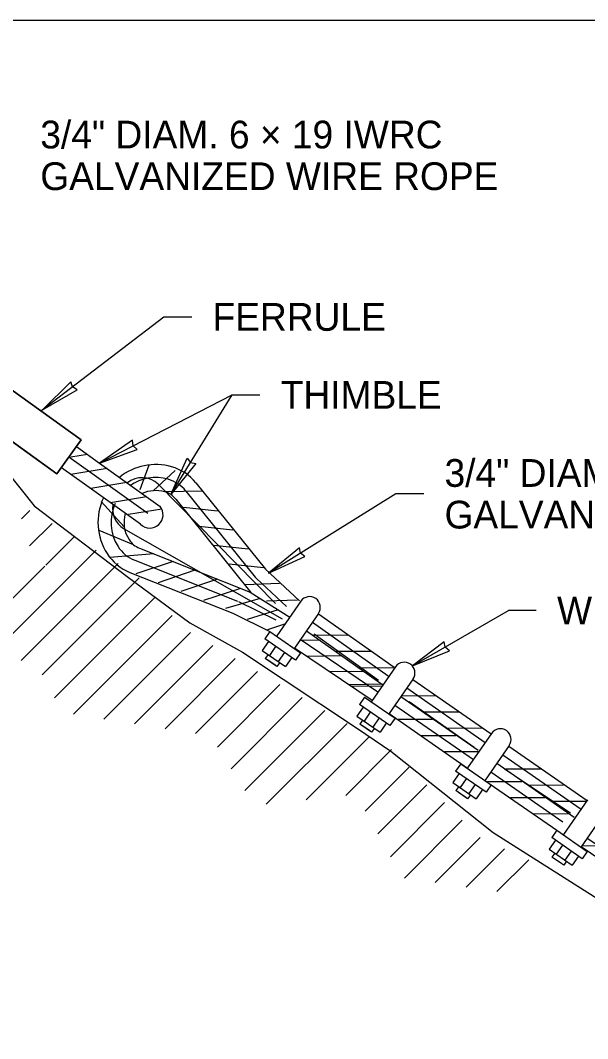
# Model space of a CAD drawing. Extents: x 99861 to 103151, y 100000 to 102076.
# Drawn here: x 102177 to 102504, y 101489 to 102076 of the extents above; entities that cross this region are included whole.
import ezdxf

# ---------------------------------------------------------------- set-up
doc = ezdxf.new("R2010")
doc.units = 0
for name, color, linetype in [('Level 1', 7, 'Continuous'), ('Level 10', 7, 'Continuous'), ('Level 15', 7, 'Continuous'), ('Level 2', 7, 'Continuous'), ('Level 20', 7, 'Continuous'), ('Level 28', 7, 'Continuous'), ('Level 4', 7, 'Continuous'), ('Level 6', 7, 'Continuous')]:
    doc.layers.add(name, color=color, linetype=linetype)

msp = doc.modelspace()

# ---------------------------------------------------------------- linework, layer by layer
at = {"layer": 'Level 1'}
for p, q in [((102272.77, 101804.76), (102312.73, 101755.09)), ((102278.62, 101809.46), (102318.58, 101759.79)), ((102266.93, 101800.05), (102310.31, 101746.26)), ((102258.12, 101795.77), (102257.97, 101795.92)), ((102246.65, 101785.56), (102246.57, 101785.62)), ((102246.07, 101771.82), (102309.84, 101746.44)), ((102243.3, 101764.85), (102302.6, 101741.33)), ((102240.54, 101757.87), (102299.83, 101734.36)), ((102318.58, 101759.79), (102338.23, 101741.48)), ((102312.73, 101755.09), (102313.46, 101754.3)), ((102313.46, 101754.3), (102330.76, 101738.18)), ((102309.84, 101746.44), (102332.64, 101732.08)), ((102303.16, 101741.08), (102324.6, 101730.46)), ((102299.83, 101734.36), (102321.26, 101723.74)), ((102349.18, 101734.05), (102392.74, 101703.2)), ((102342.24, 101724.26), (102386.33, 101693.03)), ((102346.78, 101722.36), (102383.82, 101695.69)), ((102403.55, 101696.18), (102448.69, 101664.77)), ((102396.69, 101686.33), (102441.26, 101655.32)), ((102401.4, 101683.38), (102438.84, 101657.18)), ((102389.84, 101676.48), (102435.01, 101645.05)), ((102458.83, 101657.71), (102503.96, 101626.31)), ((102451.96, 101647.87), (102496.57, 101616.83)), ((102456.42, 101644.7), (102494.31, 101619.21)), ((102445.11, 101638.02), (102486.48, 101609.23))]:
    msp.add_line(p, q, dxfattribs=at)
msp.add_lwpolyline([(99861, 100000), (103150, 100000), (103150, 102076), (99861, 102076)], close=True, dxfattribs=at)
for points in [[(102209.8, 101830.34), (102223.04, 101820.9), (102257.97, 101795.92)], [(102246.57, 101785.62), (102214.34, 101808.71), (102201.05, 101818.17)], [(102380.05, 101683.97), (102335.32, 101714.27)], [(102595.8, 101535.23), (102500.53, 101599.76)]]:
    msp.add_lwpolyline(points, dxfattribs=at)
for centre, radius, start, end in [((102255.49, 101786.67), 33.34, 74.16645, 128.84498), ((102257.03, 101792.09), 27.7, 38.8173, 74.16645), ((102255.49, 101786.67), 25.84, 74.16645, 125.28472), ((102257.03, 101792.09), 20.2, 38.8173, 74.16645), ((102255.49, 101786.67), 18.34, 74.16645, 115.23491), ((102257.03, 101792.09), 12.7, 38.8173, 74.16645), ((102255.49, 101786.67), 33.34, 154.83818, 212.69583), ((102255.49, 101786.67), 25.84, 154.83818, 212.69583), ((102251.96, 101791.13), 7.69, 226.37495, 38.53222), ((102255.49, 101786.67), 18.34, 163.64194, 212.69583), ((102250.75, 101783.63), 12.7, 212.69583, 248.36701), ((102250.75, 101783.63), 20.2, 212.69583, 248.36701), ((102250.75, 101783.63), 27.7, 212.69583, 248.36701)]:
    msp.add_arc(centre, radius, start, end, dxfattribs=at)
at = {"layer": 'Level 10'}
for p, q in [((102178.08, 101788.73), (102182.96, 101793.61)), ((102182.8, 101773.08), (102195.69, 101785.97)), ((102194.11, 101784.39), (102195.69, 101785.97)), ((102192.1, 101762.02), (102208.41, 101778.33)), ((102158.82, 101708.38), (102221.14, 101770.7)), ((102177.96, 101707.15), (102233.87, 101763.06)), ((102177.96, 101707.15), (102233.87, 101763.06)), ((102139.68, 101709.6), (102191.52, 101761.43)), ((102189.94, 101698.76), (102245.85, 101754.67)), ((102197.15, 101685.61), (102255.39, 101743.85)), ((102207.99, 101676.08), (102264.94, 101733.03)), ((102207.99, 101676.08), (102264.94, 101733.03)), ((102225.58, 101673.32), (102275.4, 101723.14)), ((102243.18, 101670.55), (102288.3, 101715.67)), ((102260.78, 101667.78), (102301.19, 101708.19)), ((102260.78, 101667.78), (102301.19, 101708.19)), ((102278.37, 101665.01), (102314.09, 101700.72)), ((102290.94, 101657.21), (102326.98, 101693.25)), ((102298.82, 101644.73), (102339.88, 101685.78)), ((102298.82, 101644.73), (102339.88, 101685.78)), ((102306.7, 101632.25), (102352.77, 101678.31)), ((102319.14, 101624.32), (102365.66, 101670.84)), ((102342.03, 101626.84), (102378.56, 101663.37)), ((102342.03, 101626.84), (102378.56, 101663.37)), ((102364.91, 101629.36), (102391.27, 101655.72)), ((102376.17, 101620.25), (102401.46, 101645.54)), ((102383.39, 101607.11), (102411.64, 101635.36)), ((102383.39, 101607.11), (102411.64, 101635.36)), ((102390.6, 101593.96), (102421.82, 101625.18)), ((102398.73, 101581.72), (102432, 101614.99)), ((102416.48, 101579.1), (102442.44, 101605.07)), ((102416.48, 101579.1), (102442.44, 101605.07)), ((102434.22, 101576.49), (102456.38, 101598.64)), ((102451.97, 101573.87), (102470.31, 101592.21))]:
    msp.add_line(p, q, dxfattribs=at)
at = {"layer": 'Level 15'}
for p, q in [((102189.31, 101850.88), (102260.16, 101905.1)), ((102260.16, 101905.1), (102276.16, 101905.1)), ((102223.04, 101820.9), (102299.47, 101860.13)), ((102264.04, 101802.68), (102299.47, 101860.13)), ((102299.47, 101860.13), (102315.47, 101860.13)), ((102393.82, 101803.16), (102320.42, 101757.49)), ((102409.82, 101803.16), (102393.82, 101803.16)), ((102403.34, 101703.92), (102458.64, 101735.85)), ((102474.64, 101735.85), (102458.64, 101735.85))]:
    msp.add_line(p, q, dxfattribs=at)
for points in [[(102190.15, 101851.52), (102210.1, 101863.03), (102207.44, 101864.76), (102206.47, 101867.77)], [(102223.04, 101820.9), (102244.72, 101828.67), (102242.41, 101830.84), (102241.99, 101833.98)], [(102264.04, 101802.68), (102273.49, 101823.68), (102275.47, 101821.22), (102278.57, 101820.55)], [(102320.42, 101757.49), (102341.38, 101767.02), (102338.91, 101768.99), (102338.23, 101772.09)], [(102403.34, 101703.92), (102424.61, 101712.75), (102422.2, 101714.81), (102421.62, 101717.92)]]:
    msp.add_lwpolyline(points, close=True, dxfattribs=at)
at = {"layer": 'Level 2'}
msp.add_lwpolyline([(102109.55, 101851.4), (102143.61, 101827.11), (102169.61, 101815.92), (102185.33, 101796.3), (102238.99, 101755.45), (102275, 101728.75), (102305.41, 101711.87), (102328.83, 101696.29), (102371.7, 101667.89), (102390.96, 101654.77), (102398.39, 101648.87), (102449.8, 101608.01), (102535.32, 101553.7), (102542.03, 101551.35)], dxfattribs=at)
at = {"layer": 'Level 28'}
for p, q in [((102339.06, 101741.26), (102325.2, 101721.28)), ((102349.17, 101734.24), (102335.32, 101714.27)), ((102321.26, 101723.74), (102338.78, 101711.55)), ((102335.88, 101707.36), (102318.34, 101719.53)), ((102320.12, 101710.57), (102318.52, 101708.26)), ((102324.5, 101715.12), (102320.94, 101709.99)), ((102329.55, 101711.75), (102325.94, 101706.53)), ((102325.26, 101703.58), (102318.52, 101708.26)), ((102324.2, 101704.32), (102320.03, 101707.21)), ((102326.86, 101705.89), (102325.26, 101703.58)), ((102333.77, 101708.83), (102330.15, 101703.61)), ((102393.58, 101703.47), (102379.72, 101683.5)), ((102403.69, 101696.45), (102389.84, 101676.48)), ((102390.4, 101669.57), (102372.87, 101681.74)), ((102375.79, 101685.95), (102393.3, 101673.76)), ((102379.02, 101677.33), (102375.47, 101672.2)), ((102374.64, 101672.78), (102373.04, 101670.47)), ((102379.79, 101665.79), (102373.04, 101670.47)), ((102378.72, 101666.53), (102374.56, 101669.42)), ((102384.08, 101673.96), (102380.46, 101668.74)), ((102388.29, 101671.04), (102384.67, 101665.82)), ((102381.38, 101668.1), (102379.79, 101665.79)), ((102448.92, 101665.11), (102435.07, 101645.14)), ((102459.04, 101658.09), (102445.18, 101638.12)), ((102431.13, 101647.59), (102448.65, 101635.4)), ((102445.74, 101631.22), (102428.21, 101643.38)), ((102429.99, 101634.42), (102428.39, 101632.11)), ((102434.37, 101638.97), (102430.81, 101633.84)), ((102439.42, 101635.6), (102435.8, 101630.38)), ((102435.13, 101627.44), (102428.39, 101632.11)), ((102434.06, 101628.18), (102429.9, 101631.06)), ((102436.73, 101629.74), (102435.13, 101627.44)), ((102443.64, 101632.68), (102440.02, 101627.46)), ((102504.27, 101626.75), (102490.41, 101606.78)), ((102514.38, 101619.74), (102500.53, 101599.76)), ((102501.09, 101592.86), (102483.55, 101605.02)), ((102486.48, 101609.23), (102503.99, 101597.05)), ((102489.71, 101600.61), (102486.16, 101595.49)), ((102485.33, 101596.06), (102483.73, 101593.75)), ((102490.47, 101589.08), (102483.73, 101593.75)), ((102494.77, 101597.24), (102491.15, 101592.02)), ((102498.98, 101594.32), (102495.36, 101589.1)), ((102489.41, 101589.82), (102485.25, 101592.7)), ((102492.07, 101591.38), (102490.47, 101589.08))]:
    msp.add_line(p, q, dxfattribs=at)
for points in [[(102321.26, 101723.74), (102318.34, 101719.53)], [(102320.45, 101718.06), (102316.83, 101712.85), (102330.15, 101703.61)], [(102338.78, 101711.55), (102335.88, 101707.36)], [(102375.79, 101685.95), (102372.87, 101681.74)], [(102374.97, 101680.27), (102371.35, 101675.06), (102384.67, 101665.82)], [(102393.3, 101673.76), (102390.4, 101669.57)], [(102431.13, 101647.59), (102428.21, 101643.38)], [(102430.32, 101641.92), (102426.7, 101636.7), (102440.02, 101627.46)], [(102448.65, 101635.4), (102445.74, 101631.22)], [(102486.48, 101609.23), (102483.55, 101605.02)], [(102485.66, 101603.56), (102482.04, 101598.34), (102495.36, 101589.1)], [(102503.99, 101597.05), (102501.09, 101592.86)]]:
    msp.add_lwpolyline(points, dxfattribs=at)
for centre in [(102344.11, 101737.75), (102398.63, 101699.96), (102453.98, 101661.6)]:
    msp.add_arc(centre, 6.15, 325.25223, 145.25223, dxfattribs=at)
at = {"layer": 'Level 4'}
for p, q in [((102216.03, 101825.9), (102206.49, 101824.29)), ((102227.41, 101817.77), (102206.54, 101814.26)), ((102251.4, 101819.65), (102246.18, 101805.52)), ((102266.71, 101816.63), (102253.99, 101804.95)), ((102238.73, 101809.58), (102218, 101806.16)), ((102324.44, 101739.87), (102256.83, 101808.72)), ((102282.36, 101804.74), (102260.5, 101804.31)), ((102237.34, 101784.06), (102224.08, 101798.8)), ((102250.21, 101801.45), (102229.3, 101797.99)), ((102258.94, 101794.36), (102239.75, 101791.18)), ((102291.11, 101793.13), (102271.42, 101795.27)), ((102242.68, 101773.82), (102222.79, 101781.93)), ((102236.93, 101783.23), (102328.35, 101731.01)), ((102299.88, 101782.23), (102280.2, 101784.36)), ((102308.66, 101771.32), (102288.98, 101773.45)), ((102254.27, 101768.49), (102228.97, 101766.51)), ((102265.47, 101764.1), (102243.89, 101757.09)), ((102277.99, 101759.12), (102256.9, 101751.92)), ((102317.43, 101760.41), (102297.75, 101762.54)), ((102290.94, 101753.96), (102269.91, 101746.76)), ((102326.82, 101751.43), (102307.03, 101750.73)), ((102304.23, 101748.67), (102282.93, 101741.6)), ((102315.68, 101742.76), (102295.57, 101737.03)), ((102337.06, 101741.88), (102319.23, 101741.25)), ((102325.93, 101736.3), (102308.12, 101730.81)), ((102329.68, 101728.12), (102319.77, 101724.78)), ((102345.71, 101729.15), (102389.27, 101698.3)), ((102346.11, 101721.88), (102365.99, 101721.78)), ((102338.34, 101718.84), (102349.76, 101719.02)), ((102359.4, 101712.47), (102379.28, 101712.37)), ((102342.33, 101709.67), (102362.21, 101709.98)), ((102355.45, 101700.66), (102375.33, 101700.97)), ((102372.69, 101703.06), (102392.57, 101702.95)), ((102366.73, 101693.35), (102386.61, 101693.65)), ((102367.89, 101692.25), (102385.47, 101692.53)), ((102416.74, 101686.63), (102396.86, 101686.57)), ((102400.12, 101691.25), (102445.26, 101659.84)), ((102393.26, 101681.4), (102438.43, 101649.97)), ((102430.11, 101677.33), (102410.23, 101677.27)), ((102395.08, 101673.2), (102414.96, 101673.26)), ((102395.08, 101673.2), (102414.96, 101673.26)), ((102408.44, 101663.9), (102428.32, 101663.96)), ((102408.44, 101663.9), (102428.32, 101663.96)), ((102443.48, 101668.03), (102423.6, 101667.97)), ((102421.81, 101654.6), (102441.69, 101654.65)), ((102421.81, 101654.6), (102441.69, 101654.65)), ((102455.4, 101652.79), (102500.53, 101621.38)), ((102448.54, 101642.94), (102489.9, 101614.16)), ((102457.17, 101644.61), (102477.05, 101644.67)), ((102457.17, 101644.61), (102477.05, 101644.67)), ((102446.55, 101637.38), (102466.43, 101637.44)), ((102446.55, 101637.38), (102466.43, 101637.44)), ((102470.54, 101635.31), (102490.42, 101635.36)), ((102470.54, 101635.31), (102490.42, 101635.36)), ((102459.91, 101628.08), (102479.79, 101628.14)), ((102459.91, 101628.08), (102479.79, 101628.14)), ((102483.91, 101626), (102503.79, 101626.06)), ((102483.91, 101626), (102503.79, 101626.06)), ((102473.28, 101618.78), (102493.16, 101618.84)), ((102473.28, 101618.78), (102493.16, 101618.84)), ((102520.57, 101600.32), (102500.69, 101600.01))]:
    msp.add_line(p, q, dxfattribs=at)
for points in [[(102250.94, 101791.72), (102218.7, 101814.81), (102205.43, 101824.26)], [(102383.42, 101688.93), (102338.68, 101719.24)], [(102574.74, 101556.74), (102503.89, 101604.73)]]:
    msp.add_lwpolyline(points, dxfattribs=at)
for centre, radius, start, end in [((102247.5, 101798.82), 13.6, 46.65433, 128.20392), ((102243.5, 101794.41), 12.97, 169.273, 239.49393)]:
    msp.add_arc(centre, radius, start, end, dxfattribs=at)
at = {"layer": 'Level 6'}
for p, q in [((102166.07, 101867.59), (102212.55, 101834.17)), ((102198.54, 101814.68), (102152.06, 101848.1)), ((102212.55, 101834.17), (102198.54, 101814.68))]:
    msp.add_line(p, q, dxfattribs=at)
msp.add_lwpolyline([(102198.54, 101814.68), (102212.55, 101834.17), (102166.07, 101867.59), (102152.06, 101848.1), (102198.54, 101814.68)], dxfattribs=at)

# ---------------------------------------------------------------- texts
at = {"layer": 'Level 20'}
for s, p in [('3/4" DIAM. 6 × 19 IWRC ', (102188.94, 102002.19)), ('GALVANIZED WIRE ROPE', (102188.94, 101978.19)), ('FERRULE', (102288.16, 101897.1)), ('THIMBLE', (102327.47, 101852.13)), ('3/4" DIAM. 6 × 19 IWRC ', (102421.82, 101807.16)), ('GALVANIZED WIRE ROPE', (102421.82, 101783.16)), ('WIRE ROPE CLIP (TYP.)', (102486.64, 101727.85))]:
    msp.add_text(s, height=16, dxfattribs=at).set_placement(p)

doc.saveas('drawing.dxf')
